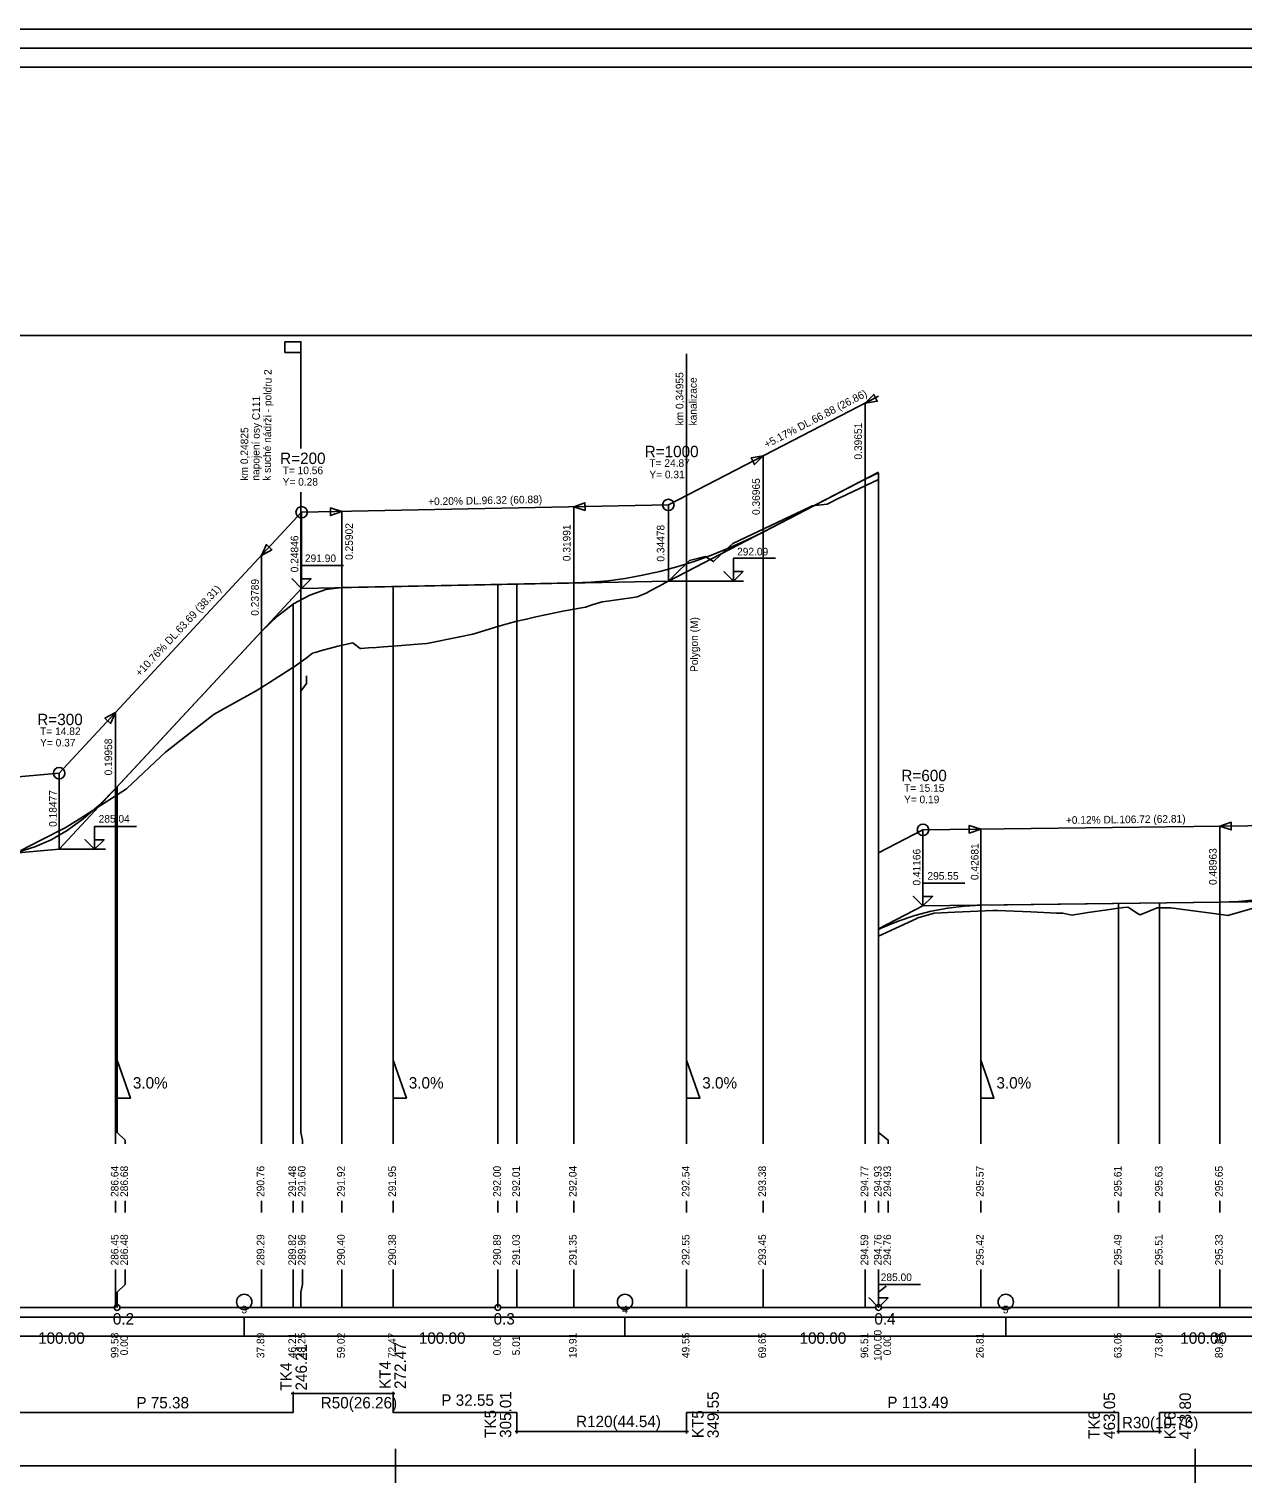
# Model space of a CAD drawing. Extents: x 999 to 1126, y 126 to 164.
# Drawn here: x 1031.87 to 1063.75, y 125.66 to 163.87 of the extents above; entities that cross this region are included whole.
import ezdxf

# ---------------------------------------------------------------- set-up
doc = ezdxf.new("R2010")
doc.units = 0
for name, color, linetype in [('KOTA', 7, 'Continuous'), ('NOVY_STAV', 7, 'Continuous'), ('NS_OBLOUK', 7, 'Continuous'), ('POPISY_NAD_TERENEM', 7, 'Continuous'), ('REZY_PO', 7, 'Continuous'), ('SESTAVY_REZU_PO', 7, 'Continuous'), ('SKLONOVE_POMERY', 7, 'Continuous'), ('SMEROVE_POMERY', 7, 'Continuous'), ('SMEROVE_POMERY_KOD', 7, 'Continuous'), ('SVK', 7, 'Continuous'), ('SVK_STAT', 7, 'Continuous'), ('TABULKY', 7, 'Continuous'), ('u_popis', 7, 'Continuous'), ('u_pricne_rezy', 7, 'Continuous'), ('x_formát_rám', 7, 'Continuous')]:
    doc.layers.add(name, color=color, linetype=linetype)

msp = doc.modelspace()

# ---------------------------------------------------------------- linework, layer by layer
at = {"layer": 'KOTA'}
for p, q in [((1048.656, 149.363), (1050.627, 149.363)), ((1032.655, 142.315), (1033.869, 142.315))]:
    msp.add_line(p, q, dxfattribs=at)
for points in [[(1039.024, 149.17), (1038.774, 149.42), (1039.024, 149.17), (1039.024, 149.77), (1040.124, 149.77)], [(1050.367, 149.363), (1050.117, 149.613), (1050.367, 149.363), (1050.367, 149.963), (1051.467, 149.963)], [(1039.024, 149.42), (1039.024, 149.17), (1039.274, 149.42), (1039.024, 149.42)], [(1039.024, 149.17), (1039.274, 149.42), (1039.024, 149.42)], [(1050.367, 149.613), (1050.367, 149.363), (1050.617, 149.613), (1050.367, 149.613)], [(1050.367, 149.363), (1050.617, 149.613), (1050.367, 149.613)], [(1039.024, 149.17), (1039.024, 149.17)], [(1050.367, 149.363), (1050.367, 149.363)], [(1033.585, 142.315), (1033.335, 142.565), (1033.585, 142.315), (1033.585, 142.915), (1034.685, 142.915)], [(1033.585, 142.565), (1033.585, 142.315), (1033.835, 142.565), (1033.585, 142.565)], [(1033.585, 142.315), (1033.835, 142.565), (1033.585, 142.565)], [(1033.585, 142.315), (1033.585, 142.315)], [(1055.344, 140.824), (1055.094, 141.074), (1055.344, 140.824), (1055.344, 141.424), (1056.444, 141.424)], [(1055.344, 141.074), (1055.344, 140.824), (1055.594, 141.074), (1055.344, 141.074)], [(1055.344, 140.824), (1055.594, 141.074), (1055.344, 141.074)], [(1055.344, 140.824), (1055.344, 140.824)], [(1054.178, 130.273), (1053.928, 130.523), (1054.178, 130.273), (1054.178, 130.873), (1055.278, 130.873)], [(1054.178, 130.273), (1054.428, 130.523), (1054.178, 130.523)]]:
    msp.add_lwpolyline(points, dxfattribs=at)
at = {"layer": 'NOVY_STAV'}
for p, q in [((1039.003, 152.846), (1039.003, 155.652)), ((1039.003, 148.869), (1039.003, 151.701))]:
    msp.add_line(p, q, dxfattribs=at)
msp.add_lwpolyline([(1038.583, 155.652), (1039.003, 155.652), (1039.003, 155.372), (1038.583, 155.372)], close=True, dxfattribs=at)
for points in [[(1048.656, 151.363), (1054.178, 154.22)], [(1054.178, 140.22), (1055.344, 140.824), (1066.016, 140.955), (1071.123, 144.689), (1079.549, 148.762), (1084.178, 152.561)], [(1014.178, 137.973), (1023.179, 139.119), (1025.684, 141.696), (1032.655, 142.315), (1039.024, 149.17), (1048.656, 149.363), (1054.178, 152.22)], [(1031.597, 142.251), (1032.02, 142.378), (1032.443, 142.565), (1032.867, 142.811), (1033.29, 143.118), (1033.713, 143.484), (1034.136, 143.909), (1037.967, 148.033), (1038.39, 148.443), (1038.812, 148.764), (1039.235, 148.996), (1039.657, 149.138), (1040.08, 149.191), (1046.169, 149.313), (1046.621, 149.332), (1047.073, 149.372), (1047.525, 149.432), (1047.977, 149.513), (1048.43, 149.614), (1048.882, 149.736), (1049.334, 149.878), (1049.786, 150.04), (1050.238, 150.223), (1050.691, 150.426), (1051.143, 150.65), (1053.829, 152.04), (1054.178, 152.208)], [(1039.024, 151.17), (1048.656, 151.363)], [(1048.656, 149.363), (1048.656, 151.363)], [(1032.655, 144.315), (1039.024, 151.17)], [(1039.024, 149.17), (1039.024, 151.17)], [(1025.684, 143.696), (1032.655, 144.315)], [(1032.655, 142.315), (1032.655, 144.315)], [(1055.344, 142.824), (1066.016, 142.955)], [(1054.178, 142.22), (1055.344, 142.824)], [(1055.344, 140.824), (1055.344, 142.824)], [(1054.178, 140.208), (1054.262, 140.248), (1054.694, 140.425), (1055.127, 140.571), (1055.56, 140.686), (1055.993, 140.769), (1056.426, 140.821), (1056.859, 140.842), (1063.141, 140.92), (1063.62, 140.94), (1064.099, 140.989)]]:
    msp.add_lwpolyline(points, dxfattribs=at)
for centre in [(1039.024, 151.17), (1048.656, 151.363), (1032.655, 144.315), (1055.344, 142.824)]:
    msp.add_circle(centre, 0.15, dxfattribs=at)
at = {"layer": 'NS_OBLOUK'}
for points in [[(1053.829, 154.04), (1054.141, 154.089), (1054.049, 154.266), (1053.829, 154.04)], [(1053.829, 152.04), (1053.829, 154.04)], [(1050.922, 152.423), (1051.143, 152.65), (1050.831, 152.601), (1050.922, 152.423)], [(1051.143, 150.65), (1051.143, 152.65)], [(1046.169, 151.313), (1046.47, 151.219), (1046.466, 151.419), (1046.169, 151.313)], [(1046.169, 149.313), (1046.169, 151.313)], [(1039.782, 151.085), (1040.08, 151.191), (1039.778, 151.285), (1039.782, 151.085)], [(1040.08, 149.191), (1040.08, 151.191)], [(1037.967, 150.033), (1038.245, 150.185), (1038.098, 150.321), (1037.967, 150.033)], [(1037.967, 148.033), (1037.967, 150.033)], [(1034.006, 145.622), (1034.137, 145.91), (1033.859, 145.758), (1034.006, 145.622)], [(1034.137, 143.91), (1034.137, 145.91)], [(1056.561, 142.739), (1056.859, 142.842), (1056.558, 142.939), (1056.561, 142.739)], [(1063.141, 142.92), (1063.442, 142.824), (1063.439, 143.023), (1063.141, 142.92)], [(1063.141, 140.92), (1063.141, 142.92)], [(1056.859, 140.842), (1056.859, 142.842)]]:
    msp.add_lwpolyline(points, dxfattribs=at)
for points in [[(1053.829, 154.04), (1054.049, 154.266), (1054.141, 154.089)], [(1051.143, 152.65), (1050.831, 152.601), (1050.922, 152.423)], [(1046.169, 151.313), (1046.466, 151.419), (1046.47, 151.219)], [(1040.08, 151.191), (1039.778, 151.285), (1039.782, 151.085)], [(1037.967, 150.033), (1038.098, 150.321), (1038.245, 150.185)], [(1034.137, 145.91), (1033.859, 145.758), (1034.006, 145.622)], [(1056.859, 142.842), (1056.558, 142.939), (1056.561, 142.739)], [(1063.141, 142.92), (1063.439, 143.023), (1063.442, 142.824)]]:
    msp.add_lwpolyline(points, close=True, dxfattribs=at)
at = {"layer": 'POPISY_NAD_TERENEM'}
for points in [[(1038.799, 146.273), (1038.799, 146.873)], [(1039.003, 146.273), (1039.003, 146.473), (1039.149, 146.673), (1039.149, 146.873)], [(1041.425, 146.273), (1041.425, 146.873)], [(1049.133, 146.273), (1049.133, 146.873)]]:
    msp.add_lwpolyline(points, dxfattribs=at)
at = {"layer": 'REZY_PO'}
for points in [[(1031.651, 142.284), (1032.178, 142.553), (1032.812, 142.875), (1033.178, 143.109), (1034.178, 143.748), (1034.178, 143.748), (1034.423, 143.905), (1035.178, 144.612), (1035.451, 144.867), (1036.178, 145.438), (1036.725, 145.867), (1037.178, 146.117), (1037.828, 146.477), (1038.178, 146.699), (1038.763, 147.07), (1038.799, 147.094), (1038.799, 147.094), (1038.799, 147.094), (1038.988, 147.226), (1039.178, 147.365), (1039.308, 147.464), (1039.378, 147.486), (1039.578, 147.546), (1039.778, 147.602), (1039.978, 147.653), (1040.178, 147.699), (1040.363, 147.739), (1040.378, 147.727), (1040.563, 147.592), (1040.578, 147.593), (1040.778, 147.604), (1040.978, 147.616), (1041.178, 147.631), (1041.301, 147.64), (1041.425, 147.65), (1041.425, 147.65), (1041.425, 147.65), (1042.178, 147.713), (1042.309, 147.723), (1043.178, 147.897), (1043.524, 147.966), (1044.178, 148.167), (1044.42, 148.241), (1044.679, 148.305), (1044.929, 148.365), (1045.178, 148.422), (1045.428, 148.477), (1045.678, 148.529), (1045.928, 148.579), (1046.178, 148.626), (1046.428, 148.67), (1046.484, 148.68), (1046.678, 148.743), (1046.915, 148.819), (1046.928, 148.82), (1047.178, 148.855), (1047.428, 148.89), (1047.678, 148.925), (1047.836, 148.946), (1047.928, 148.985), (1048.09, 149.054), (1048.178, 149.102), (1048.417, 149.232), (1048.652, 149.359), (1048.656, 149.363), (1048.895, 149.596), (1049.133, 149.828), (1049.133, 149.828), (1049.133, 149.828), (1049.178, 149.871), (1049.212, 149.904), (1049.624, 150.011), (1049.842, 149.873), (1050.178, 150.189), (1050.35, 150.351), (1051.178, 150.745), (1052.178, 151.22), (1052.434, 151.342), (1052.825, 151.381), (1053.152, 151.55), (1053.178, 151.562), (1054.178, 152.029), (1054.178, 152.029)], [(1054.178, 140.029), (1054.178, 140.029), (1055.178, 140.497), (1055.184, 140.5), (1055.641, 140.638), (1056.178, 140.661), (1057.178, 140.703), (1057.3, 140.708), (1058.178, 140.669), (1058.854, 140.639), (1059.021, 140.632), (1059.178, 140.597), (1059.255, 140.58), (1059.681, 140.653), (1060.178, 140.723), (1060.483, 140.766), (1060.622, 140.784), (1060.725, 140.795), (1060.761, 140.771), (1060.9, 140.679), (1061.038, 140.588), (1061.039, 140.589), (1061.178, 140.646), (1061.305, 140.699), (1061.432, 140.752), (1061.493, 140.778), (1061.558, 140.778), (1061.558, 140.778), (1061.558, 140.778), (1061.855, 140.776), (1062.178, 140.733), (1063.178, 140.599), (1063.354, 140.576), (1064.178, 140.806)]]:
    msp.add_lwpolyline(points, dxfattribs=at)
at = {"layer": 'SESTAVY_REZU_PO'}
for points in [[(1024.253, 130.273), (1034.103, 130.273)], [(1034.253, 130.273), (1044.103, 130.273)], [(1044.253, 130.273), (1054.103, 130.273)], [(1054.253, 130.273), (1064.103, 130.273)]]:
    msp.add_lwpolyline(points, dxfattribs=at)
for centre in [(1034.178, 130.273), (1044.178, 130.273), (1054.178, 130.273)]:
    msp.add_circle(centre, 0.075, dxfattribs=at)
at = {"layer": 'SKLONOVE_POMERY'}
for points in [[(1034.178, 135.773), (1034.178, 136.773), (1034.178, 136.773), (1034.353, 136.273), (1034.528, 135.773), (1034.178, 135.773)], [(1041.425, 135.773), (1041.425, 136.773), (1041.425, 136.773), (1041.6, 136.273), (1041.775, 135.773), (1041.425, 135.773)], [(1049.133, 135.773), (1049.133, 136.773), (1049.133, 136.773), (1049.308, 136.273), (1049.483, 135.773), (1049.133, 135.773)], [(1056.859, 135.773), (1056.859, 136.773), (1056.859, 136.773), (1057.034, 136.273), (1057.209, 135.773), (1056.859, 135.773)]]:
    msp.add_lwpolyline(points, dxfattribs=at)
at = {"layer": 'SMEROVE_POMERY'}
msp.add_lwpolyline([(1031.261, 127.51), (1038.799, 127.51), (1038.799, 128.01), (1041.425, 128.01), (1041.425, 127.51), (1044.679, 127.51), (1044.679, 127.01), (1049.133, 127.01), (1049.133, 127.51), (1060.483, 127.51), (1060.483, 127.01), (1061.558, 127.01), (1061.558, 127.51), (1067.362, 127.51)], dxfattribs=at)
at = {"layer": 'SMEROVE_POMERY_KOD'}
for points in [[(1038.749, 128.01), (1038.849, 128.01)], [(1038.799, 127.96), (1038.799, 128.06)], [(1041.375, 128.01), (1041.475, 128.01)], [(1041.425, 127.96), (1041.425, 128.06)], [(1044.629, 127.01), (1044.729, 127.01)], [(1044.679, 126.96), (1044.679, 127.06)], [(1049.083, 127.01), (1049.183, 127.01)], [(1049.133, 126.96), (1049.133, 127.06)], [(1060.433, 127.01), (1060.533, 127.01)], [(1060.483, 126.96), (1060.483, 127.06)], [(1061.508, 127.01), (1061.608, 127.01)], [(1061.558, 126.96), (1061.558, 127.06)]]:
    msp.add_lwpolyline(points, dxfattribs=at)
at = {"layer": 'SVK'}
for points in [[(1054.178, 134.573), (1054.178, 152.208)], [(1054.178, 132.773), (1054.178, 133.073)], [(1054.178, 130.273), (1054.178, 131.273)]]:
    msp.add_lwpolyline(points, dxfattribs=at)
at = {"layer": 'SVK_STAT'}
for points in [[(1053.829, 134.573), (1053.828, 152.039)], [(1051.143, 134.573), (1051.143, 150.65)], [(1049.133, 134.573), (1049.133, 149.815)], [(1040.08, 134.573), (1040.08, 149.191)], [(1041.425, 134.573), (1041.425, 149.218)], [(1044.178, 134.573), (1044.178, 149.273)], [(1044.679, 134.573), (1044.679, 149.283)], [(1046.169, 134.573), (1046.169, 149.313)], [(1038.799, 134.573), (1038.799, 148.754)], [(1039.049, 134.573), (1039.049, 134.673), (1039.003, 134.873), (1039.003, 148.869)], [(1037.967, 134.573), (1037.968, 148.034)], [(1034.137, 134.573), (1034.137, 143.91)], [(1034.387, 134.573), (1034.387, 134.673), (1034.178, 134.873), (1034.178, 143.954)], [(1054.428, 134.573), (1054.428, 134.673), (1054.178, 134.873), (1054.178, 142.208)], [(1056.859, 134.573), (1056.859, 140.842)], [(1060.483, 134.573), (1060.483, 140.887)], [(1061.558, 134.573), (1061.558, 140.9)], [(1063.141, 134.573), (1063.141, 140.92)], [(1034.137, 132.773), (1034.137, 133.073)], [(1034.387, 132.773), (1034.387, 133.073)], [(1037.967, 132.773), (1037.967, 133.073)], [(1038.799, 132.773), (1038.799, 133.073)], [(1039.049, 132.773), (1039.049, 133.073)], [(1040.08, 132.773), (1040.08, 133.073)], [(1041.425, 132.773), (1041.425, 133.073)], [(1044.178, 132.773), (1044.178, 133.073)], [(1044.679, 132.773), (1044.679, 133.073)], [(1046.169, 132.773), (1046.169, 133.073)], [(1049.133, 132.773), (1049.133, 133.073)], [(1051.143, 132.773), (1051.143, 133.073)], [(1053.829, 132.773), (1053.829, 133.073)], [(1054.428, 132.773), (1054.428, 133.073)], [(1056.859, 132.773), (1056.859, 133.073)], [(1060.483, 132.773), (1060.483, 133.073)], [(1061.558, 132.773), (1061.558, 133.073)], [(1063.141, 132.773), (1063.141, 133.073)], [(1034.137, 130.273), (1034.137, 131.273)], [(1034.178, 130.273), (1034.178, 130.673), (1034.387, 130.873), (1034.387, 131.273)], [(1037.967, 130.273), (1037.967, 131.273)], [(1038.799, 130.273), (1038.799, 131.273)], [(1039.003, 130.273), (1039.003, 130.673), (1039.049, 130.873), (1039.049, 131.273)], [(1040.08, 130.273), (1040.08, 131.273)], [(1041.425, 130.273), (1041.425, 131.273)], [(1044.178, 130.273), (1044.178, 131.273)], [(1044.679, 130.273), (1044.679, 131.273)], [(1046.169, 130.273), (1046.169, 131.273)], [(1049.133, 130.273), (1049.133, 131.273)], [(1051.143, 130.273), (1051.143, 131.273)], [(1053.829, 130.273), (1053.829, 131.273)], [(1056.859, 130.273), (1056.859, 131.273)], [(1060.483, 130.273), (1060.483, 131.273)], [(1061.558, 130.273), (1061.558, 131.273)], [(1063.141, 130.273), (1063.141, 131.273)], [(1054.178, 130.273), (1054.178, 130.673), (1054.378, 130.834), (1054.378, 130.834)]]:
    msp.add_lwpolyline(points, dxfattribs=at)
at = {"layer": 'TABULKY'}
for points in [[(1014.178, 162.868), (1100.556, 162.868), (1100.556, 163.868), (1014.178, 163.868), (1014.178, 162.868)], [(1014.178, 163.368), (1100.556, 163.368)]]:
    msp.add_lwpolyline(points, dxfattribs=at)
at = {"layer": 'u_popis'}
msp.add_lwpolyline([(1049.133, 148.976), (1049.133, 155.334)], dxfattribs=at)
at = {"layer": 'u_pricne_rezy'}
for points in [[(1017.517, 129.52), (1103.895, 129.52), (1103.895, 130.02), (1017.517, 130.02), (1017.517, 129.52)], [(1037.517, 129.52), (1037.517, 130.02)], [(1047.517, 129.52), (1047.517, 130.02)], [(1057.517, 129.52), (1057.517, 130.02)]]:
    msp.add_lwpolyline(points, dxfattribs=at)
for centre in [(1037.517, 130.42), (1047.517, 130.42), (1057.517, 130.42)]:
    msp.add_circle(centre, 0.2, dxfattribs=at)
at = {"layer": 'x_formát_rám'}
for p, q in [((1041.491, 125.663), (1041.491, 126.563)), ((1062.491, 125.663), (1062.491, 126.563))]:
    msp.add_line(p, q, dxfattribs=at)
msp.add_lwpolyline([(999.491, 126.113), (1125.491, 126.113), (1125.491, 155.813), (999.491, 155.813)], close=True, dxfattribs=at)

# ---------------------------------------------------------------- texts
at = {"layer": 'KOTA'}
for s, p in [('292.09', (1050.461, 150.036)), ('291.90', (1039.11, 149.861)), ('285.04', (1033.692, 143.015)), ('295.55', (1055.461, 141.514)), ('285.00', (1054.234, 130.967))]:
    msp.add_text(s, height=0.2, dxfattribs=at).set_placement(p)
at = {"layer": 'NOVY_STAV'}
for s, rotation, p in [('k suché nádrži - poldru 2', 89.5404, (1038.213, 151.998)), ('+5.17% DL.66.88 (26.86)', 27.359, (1051.237, 152.851)), ('napojení osy C111', 89.5404, (1037.913, 152)), ('km 0,24825', 89.5404, (1037.613, 152.003)), ('+0.20% DL.96.32 (60.88)', 1.1457, (1042.348, 151.353)), (' 0.24846', 90, (1038.937, 149.518)), (' 0.34478', 90, (1048.553, 149.798)), ('+10.76% DL.63.69 (38.31)', 47.1085, (1034.781, 146.839)), (' 0.18477', 90, (1032.592, 142.828)), ('+0.12% DL.106.72 (62.81)', 0.7064, (1059.098, 142.98)), (' 0.41166', 90, (1055.278, 141.286))]:
    msp.add_text(s, height=0.2, rotation=rotation, dxfattribs=at).set_placement(p)
at = {"layer": 'NS_OBLOUK'}
for s, p in [(' 0.39651', (1053.74, 152.482)), (' 0.36965', (1051.06, 151.024)), (' 0.25902', (1040.37, 149.844)), (' 0.31991', (1046.086, 149.81)), (' 0.23789', (1037.898, 148.377)), (' 0.19958', (1034.047, 144.182)), (' 0.42681', (1056.802, 141.43)), (' 0.48963', (1063.058, 141.301))]:
    msp.add_text(s, height=0.2, rotation=90, dxfattribs=at).set_placement(p)
for s, height, p in [('R=1000', 0.3, (1048.034, 152.617)), ('R=200', 0.3, (1038.459, 152.438)), ('T= 24.87', 0.2, (1048.156, 152.363)), ('T= 10.56', 0.2, (1038.524, 152.17)), ('Y= 0.28', 0.2, (1038.524, 151.87)), ('Y= 0.31', 0.2, (1048.156, 152.063)), ('R=300', 0.3, (1032.081, 145.576)), ('T= 14.82', 0.2, (1032.155, 145.315)), ('Y= 0.37', 0.2, (1032.155, 145.015)), ('R=600', 0.3, (1054.776, 144.102)), ('T= 15.15', 0.2, (1054.844, 143.824)), ('Y= 0.19', 0.2, (1054.844, 143.524))]:
    msp.add_text(s, height=height, dxfattribs=at).set_placement(p)
at = {"layer": 'POPISY_NAD_TERENEM'}
msp.add_text('Polygon (M)', height=0.2, rotation=90, dxfattribs=at).set_placement((1049.433, 146.973))
at = {"layer": 'SESTAVY_REZU_PO'}
for s, p in [('0.2', (1034.066, 129.825)), ('0.3', (1044.066, 129.825)), ('0.4', (1054.066, 129.825))]:
    msp.add_text(s, height=0.3, dxfattribs=at).set_placement(p)
at = {"layer": 'SKLONOVE_POMERY'}
for p in [(1034.592, 136.026), (1041.838, 136.026), (1049.547, 136.026), (1057.273, 136.026)]:
    msp.add_text('3.0%', height=0.3, dxfattribs=at).set_placement(p)
at = {"layer": 'SMEROVE_POMERY'}
for s, p in [('P 32.55', (1042.691, 127.689)), ('P 75.38', (1034.683, 127.622)), ('R50(26.26)', (1039.525, 127.621)), ('P 113.49', (1054.406, 127.629)), ('R120(44.54)', (1046.231, 127.129)), ('R30(10.76)', (1060.569, 127.098))]:
    msp.add_text(s, height=0.3, dxfattribs=at).set_placement(p)
at = {"layer": 'SMEROVE_POMERY_KOD'}
for s, p in [('246.21', (1039.164, 128.09)), ('272.47', (1041.763, 128.131)), ('TK4', (1038.764, 128.09)), ('KT4', (1041.363, 128.131)), ('305.01', (1044.53, 126.846)), ('349.55', (1049.98, 126.839)), ('463.05', (1060.388, 126.819)), ('473.80', (1062.381, 126.809)), ('TK5', (1044.13, 126.846)), ('KT5', (1049.58, 126.839)), ('TK6', (1059.988, 126.819)), ('KT6', (1061.981, 126.809))]:
    msp.add_text(s, height=0.3, rotation=90, dxfattribs=at).set_placement(p)
at = {"layer": 'SVK'}
for s, p in [(' 294.93', (1054.255, 133.103)), (' 294.76', (1054.255, 131.303)), ('100.00', (1054.255, 128.867))]:
    msp.add_text(s, height=0.2, rotation=90, dxfattribs=at).set_placement(p)
at = {"layer": 'SVK_STAT'}
for s, p in [(' 286.64', (1034.213, 133.103)), (' 286.68', (1034.463, 133.103)), (' 290.76', (1038.044, 133.103)), (' 291.48', (1038.875, 133.103)), (' 291.60', (1039.125, 133.103)), (' 291.92', (1040.157, 133.103)), (' 291.95', (1041.501, 133.103)), (' 292.00', (1044.255, 133.103)), (' 292.01', (1044.756, 133.103)), (' 292.04', (1046.245, 133.103)), (' 292.54', (1049.21, 133.103)), (' 293.38', (1051.22, 133.103)), (' 294.77', (1053.905, 133.103)), (' 294.93', (1054.505, 133.103)), (' 295.57', (1056.936, 133.103)), (' 295.61', (1060.559, 133.103)), (' 295.63', (1061.635, 133.103)), (' 295.65', (1063.217, 133.103)), (' 286.45', (1034.213, 131.303)), (' 286.48', (1034.463, 131.303)), (' 289.29', (1038.044, 131.303)), (' 289.82', (1038.875, 131.303)), (' 289.96', (1039.125, 131.303)), (' 290.40', (1040.157, 131.303)), (' 290.38', (1041.501, 131.303)), (' 290.89', (1044.255, 131.303)), (' 291.03', (1044.756, 131.303)), (' 291.35', (1046.245, 131.303)), (' 292.55', (1049.21, 131.303)), (' 293.45', (1051.22, 131.303)), (' 294.59', (1053.905, 131.303)), (' 294.76', (1054.505, 131.303)), (' 295.42', (1056.936, 131.303)), (' 295.49', (1060.559, 131.303)), (' 295.51', (1061.635, 131.303)), (' 295.33', (1063.217, 131.303)), (' 99.58', (1034.213, 128.867)), ('  0.00', (1034.463, 128.867)), (' 37.89', (1038.044, 128.867)), (' 46.21', (1038.875, 128.867)), (' 48.25', (1039.125, 128.867)), (' 59.02', (1040.157, 128.867)), (' 72.47', (1041.501, 128.867)), ('  0.00', (1044.255, 128.867)), ('  5.01', (1044.756, 128.867)), (' 19.91', (1046.245, 128.867)), (' 49.55', (1049.21, 128.867)), (' 69.65', (1051.22, 128.867)), (' 96.51', (1053.905, 128.867)), ('  0.00', (1054.505, 128.867)), (' 26.81', (1056.936, 128.867)), (' 63.05', (1060.559, 128.867)), (' 73.80', (1061.635, 128.867)), (' 89.63', (1063.217, 128.867))]:
    msp.add_text(s, height=0.2, rotation=90, dxfattribs=at).set_placement(p)
at = {"layer": 'u_popis'}
for s, p in [('km 0,34955', (1049.051, 153.452)), ('kanalizace', (1049.401, 153.452))]:
    msp.add_text(s, height=0.2, rotation=90, dxfattribs=at).set_placement(p)
at = {"layer": 'u_pricne_rezy'}
for s, height, p in [('3', 0.2, (1037.442, 130.12)), ('4', 0.2, (1047.442, 130.12)), ('5', 0.2, (1057.442, 130.12)), ('100.00', 0.3, (1032.102, 129.32)), ('100.00', 0.3, (1042.102, 129.32)), ('100.00', 0.3, (1052.102, 129.32)), ('100.00', 0.3, (1062.102, 129.32))]:
    msp.add_text(s, height=height, dxfattribs=at).set_placement(p)

doc.saveas('drawing.dxf')
